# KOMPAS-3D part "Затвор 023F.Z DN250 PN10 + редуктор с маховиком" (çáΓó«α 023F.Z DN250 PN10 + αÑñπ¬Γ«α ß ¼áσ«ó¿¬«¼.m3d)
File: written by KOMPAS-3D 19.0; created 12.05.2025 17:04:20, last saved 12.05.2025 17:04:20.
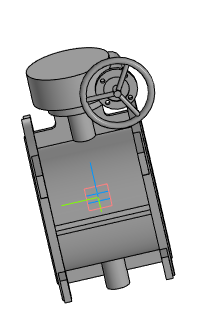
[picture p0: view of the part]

Document properties: Полное имя файла: Затвор 023F.Z DN250 PN10 + редуктор с маховиком.a3d

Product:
- Part/product: Затвор 023F.Z DN250 PN10 + редуктор с маховиком
    Масса: 76.0895

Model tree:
1. Операция без истории:1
